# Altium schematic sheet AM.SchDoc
size B
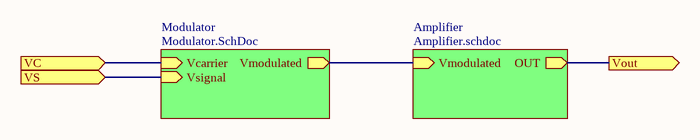
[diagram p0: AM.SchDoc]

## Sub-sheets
Amplifier = Amplifier.schdoc: Vmodulated (in), OUT (out)
Modulator = Modulator.SchDoc: Vmodulated (out), Vcarrier (in), Vsignal (in)

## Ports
VC (in), Vout (out), VS (in)

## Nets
VC: port VC, sheet Modulator/Vcarrier
Vout: port Vout, sheet Amplifier/OUT
VS: port VS, sheet Modulator/Vsignal
(unnamed): sheet Amplifier/Vmodulated, sheet Modulator/Vmodulated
